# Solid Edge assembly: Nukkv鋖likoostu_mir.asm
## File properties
Author: Türk
Template: Iso Assembly.asm
Last saved by: Türk
Revision: 6
Application: Solid Edge
Username: Türk
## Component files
ll_mir.par
Saalenukk.par
llihammasratas.par
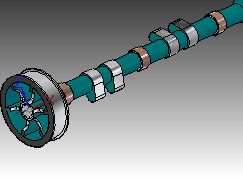
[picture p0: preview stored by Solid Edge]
